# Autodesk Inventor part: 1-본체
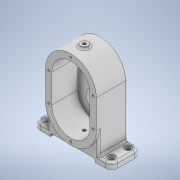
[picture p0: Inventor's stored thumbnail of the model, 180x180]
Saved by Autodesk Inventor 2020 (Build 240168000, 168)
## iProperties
Created: 2021-05
Part Number: 1-본체
Material: 일반
Document SubType Name: Modeling
Designer: Owner
Density: 1 g/cm^3
Appearance: 기본값
Author: Owner
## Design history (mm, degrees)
sketch "스케치2"
  geometry: L1 (0, 0)-(0, -45); L2 (-40, 0)-(-40, -45); L3 (40, -45)-(40, 0); A1 r 40 centre (0, 0) between (40, 0) and (-40, 0); A2 r 40 centre (0, -45) between (-40, -45) and (40, -45); 2 further points
  constraints: 8 end point, 4 point on circle, 4 tangent, 2 centre point, 1 coincident, 1 midpoint, 1 parallel, 1 vertical
  dimensions: "d12" = 45 distance of L1.start L1.end; "d13" = 80 distance between parallel lines of L3 L2
extrude "돌출3" new body sketch "스케치2" distance "d14" = 21; taper "d16" = 0 deg; dims "d15" = 28, "d17" = 0
sketch "스케치6"
  geometry: L1 (0, 0)-(0, -45); L2 (-30, 0)-(-30, -45); L3 (30, -45)-(30, 0); A1 r 30 centre (0, 0) between (30, 0) and (-30, 0); A2 r 30 centre (0, -45) between (-30, -45) and (30, -45); A3 r 40 centre (0, -45) between (-40, -45) and (40, -45) reference; 1 further point
  constraints: 8 end point, 4 point on circle, 4 tangent, 2 centre point, 1 coincident, 1 midpoint, 1 parallel, 1 vertical
  dimensions: "d18" = 30 radius of A1
extrude "돌출4" cut sketch "스케치6" distance "d19" = 41; taper "d20" = 0 deg
node "작업 평면4"
sketch "스케치8"
  geometry: L1 (-61, -28)-(61, -28); L2 (61, -28)-(61, 18); L3 (61, 18)-(-61, 18); L4 (-61, 18)-(-61, -28); L5 (-61, -28)-(61, 18); L6 (61, -28)-(-61, 18); L7 (-40, -28)-(40, -28) reference; L8 (0, 0)-(0, -58.176); 1 further point
  constraints: 14 end point, 2 midpoint, 2 parallel, 1 collinear, 1 horizontal, 1 perpendicular, 1 vertical, 1 other
  dimensions: "d26" = 122 distance of L1.start L1.end; "d27" = 46 distance of L1.end L2.end
extrude "돌출6" join sketch "스케치8" distance "d28" = 10; taper "d29" = 0 deg
sketch "스케치9"
  geometry: L1 (21, 47)-(21, 10); L2 (0, 10)-(45.801, 10) reference; L3 (61, 102.696)-(61, -8.083); L4 (101, 47)-(101, 10); L5 (76.199, 10)-(122, 10) reference; A1 r 40 centre (61, 47) between (21, 47) and (101, 47) reference; 1 further point
  constraints: 6 end point, 2 point on line, 2 symmetric about line, 2 vertical, 1 coincident
extrude "돌출7" join sketch "스케치9" distance "d30" = 46; taper "d31" = 0 deg
extrude "돌출8" join sketch "스케치9" distance "d32" = 46; taper "d33" = 0 deg
node "작업 평면5"
sketch "스케치10"
  geometry: C1 r 6 at (0, 0); 1 further point
  constraints: 1 centre point, 1 coincident
  dimensions: "d36" = 12 diameter of C1
extrude "돌출9" join sketch "스케치10" stored distance "d37" = 46; taper "d38" = 0 deg
sketch "스케치11"
  geometry: C1 r 6 at (0, 0) reference; 2 further points
  constraints: 1 coincident
hole "구멍1" sketch "스케치11" at (0, 0) diameter "d39" = 4.917; stored, may be unused: countersink angle "d43" = 90 deg, drill point angle "d45" = 0 deg; dims "d40" = 12, "d41" = 12.6, "d42" = 2, "d44" = 17.1
fillet "모깎기1" dims "d46" = 10
sketch "스케치13"
  geometry: A1 r 10 centre (-51, 18) between (-51, 28) and (-61, 18) reference; A2 r 10 centre (51, 18) between (61, 18) and (51, 28) reference; A3 r 10 centre (51, -8) between (51, -18) and (61, -8) reference; A4 r 10 centre (-51, -8) between (-61, -8) and (-51, -18) reference; 1 further point
hole "구멍2" sketch "스케치13" at (-51, 18), (-51, -8), (51, -8), (51, 18) diameter "d47" = 6.6; stored, may be unused: countersink angle "d51" = 90 deg, drill point angle "d53" = 0 deg; dims "d48" = 12, "d49" = 11, "d50" = 2, "d52" = 17.1
sketch "스케치14"
  geometry: L1 (51, -28)-(-51, -28) reference; L2 (-51, 18)-(51, 18) reference; L3 (0, -51.959)-(0, 89.002); L4 (35, -28)-(35, 18); L5 (-35, -28)-(-35, 18); 1 further point
  constraints: 6 end point, 5 point on line, 3 vertical, 1 other
  dimensions: "d54" = 70 distance between parallel lines of L5 L4
extrude "돌출10" cut sketch "스케치14" distance "d55" = 5; taper "d56" = 0 deg
sketch "스케치15"
  geometry: L1 (0, 0)-(0, -45); L2 (-26, 0)-(-26, -45); L3 (26, -45)-(26, 0); A1 r 26 centre (0, 0) between (26, 0) and (-26, 0); A2 r 26 centre (0, -45) between (-26, -45) and (26, -45); 2 further points
  constraints: 8 end point, 4 point on circle, 4 tangent, 2 centre point, 1 coincident, 1 midpoint, 1 parallel, 1 vertical
  dimensions: "d57" = 52 distance between parallel lines of L3 L2; "d58" = 45 distance of L1.start L1.end
extrude "돌출11" join sketch "스케치15" distance "d59" = 11; taper "d60" = 0 deg
sketch "스케치16"
  geometry: L1 (-26, 0)-(-26, -45) reference; L2 (26, -45)-(26, 0) reference; L3 (-26, -45)-(-26, 0) reference; L4 (-26, -30)-(26, -30); A1 r 26 centre (0, 0) between (26, 0) and (-26, 0) reference; 2 further points
  constraints: 2 end point, 2 point on line, 1 perpendicular
  dimensions: "d61" = 30 distance from line of L4 point (0, 0)
extrude "돌출12" cut sketch "스케치16" distance "d62" = 3; taper "d63" = 0 deg
sketch "스케치17" dims "d64" = 40
  geometry: 3 further points
  constraints: 2 vertical alignment, 1 coincident, 2 other
hole "구멍3" sketch "스케치17" at (0, 20) diameter "d65" = 3.242; stored, may be unused: countersink angle "d69" = 90 deg, drill point angle "d71" = 118 deg; dims "d66" = 8, "d67" = 12.24, "d68" = 3.58, "d70" = 10
sketch "스케치18"
  geometry: L1 (0, 0)-(0, -48.739); L2 (0, -20)-(30, -20) reference; L3 (14, -20)-(14, -28); L4 (14, -28)-(11, -28); L5 (11, -28)-(11, -32); L6 (11, -32)-(14, -32); L7 (14, -32)-(14, -36); L8 (26, -36)-(0, -36) reference; L9 (14, -20)-(0, -20); L10 (0, -28)-(0, -36) reference; L11 (14, -36)-(0, -36)
  constraints: 16 end point, 7 perpendicular, 2 point on line, 1 collinear, 1 vertical
  dimensions: "d75" = 28 diameter of L3 L1; "d76" = 22 diameter of L5 L1; "d77" = 8 distance of L3.start L3.end; "d78" = 4 distance of L6.end L7.end
revolve "회전2" sketch "스케치18" stored, may be unused: angle "d80" = 90 deg
sketch "스케치19"
  geometry: L1 (-45, 21)-(-45, -20) reference; L2 (-45, -20)-(0, -20) reference; L3 (-45, -20)-(-45, -47.398); L4 (-31, -20)-(-31, -28); L5 (-31, -28)-(-35, -28); L6 (-35, -28)-(-35, -32); L7 (-35, -32)-(-45, -32); 1 further point
  constraints: 10 end point, 3 perpendicular, 2 point on line, 2 vertical
  dimensions: "d81" = 8 distance of L4.start L4.end; "d82" = 28 diameter of L4 L3; "d83" = 20 diameter of L6 L3; "d84" = 4 distance of L5.end L6.end
revolve "회전3" sketch "스케치19" stored, may be unused: angle "d85" = 90 deg
sketch "스케치20"
  geometry: L1 (40, 21)-(-40, 21) reference; 2 further points
  constraints: 1 coincident
  dimensions: "d86" = 21 distance from line of point (0, 0) L1
hole "구멍4" sketch "스케치20" at (0, 0) diameter "d87" = 4.917; stored, may be unused: countersink angle "d91" = 90 deg, drill point angle "d93" = 0 deg; dims "d88" = 12, "d89" = 12, "d90" = 1, "d92" = 17.1
sketch "스케치21"
  geometry: L1 (0, 0)-(0, -101.673); L2 (-87.317, -80)-(87.317, -80); L3 (-51, -92)-(-35, -92) reference
  constraints: 4 end point, 2 horizontal, 1 symmetric about line, 1 vertical
  dimensions: "d94" = 12 distance between parallel lines of L3 L2
feature "엠보싱1" sketch "스케치21" dims "d12" = 45, "d13" = 80, "d95" = 0.5, "d96" = 0
fillet "모깎기2" dims "d97" = 3
sketch "스케치22"
  geometry: L1 (0, 0)-(0, -45); L2 (-35, 0)-(-35, -45); L3 (35, -45)-(35, 0); L4 (-52.867, -22.5)-(54.021, -22.5); A1 r 35 centre (0, 0) between (35, 0) and (-35, 0); A2 r 35 centre (0, -45) between (-35, -45) and (35, -45); 8 further points
  constraints: 10 end point, 5 point on circle, 4 tangent, 3 coincident, 3 symmetric about line, 2 centre point, 1 horizontal, 1 midpoint, 1 parallel, 1 point on line, 1 vertical, 1 vertical alignment
  dimensions: "d98" = 35 radius of A1; "d99" = 45 distance of L1.start L1.end
hole "구멍5" sketch "스케치22" at (0, 35), (-35, 0), (35, 0), (0, -80), (-35, -45), (35, -45) diameter "d100" = 3.242; stored, may be unused: countersink angle "d104" = 90 deg, drill point angle "d106" = 118 deg; dims "d101" = 8, "d102" = 12, "d103" = 1, "d105" = 10
chamfer "모따기1" distance "d107" = 3; stored, may be unused: second distance "d108" = 2, angle "d109" = 45 deg
fillet "모깎기3" dims "d110" = 0.3
chamfer "모따기2" distance "d111" = 1; stored, may be unused: second distance "d112" = 2, angle "d113" = 45 deg
fillet "모깎기4" dims "d114" = 3
fillet "모깎기5" dims "d115" = 3
fillet "모깎기6" dims "d116" = 3
fillet "모깎기7" dims "d117" = 3
fillet "모깎기8" dims "d118" = 3
fillet "모깎기9" dims "d119" = 3
node "솔리드2"
pattern_circular "원형 패턴1" dims angle "d73" = 360 deg
feature "A9D066F2-1C7D-4E18-AEED-F7BC21143FA4" dims "d47" = 6.6, "d48" = 12, "d49" = 11, "d50" = 2, "d51" = 90 deg, "d52" = 17.1, "d53" = 0
other parameters: "d21" = -92, "d34" = -135
